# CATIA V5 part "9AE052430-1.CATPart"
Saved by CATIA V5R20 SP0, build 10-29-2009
Part number: 9AE052430-1
Revision: ANY
Definition: UNKNOWN
Nomenclature: 9AE052430-1
Source: Unknown
Bounding box of the stored display mesh (mm): x -8 to 8, y 0 to 76.999, z -8 to 8
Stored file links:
  C:\Users\Utente\Desktop\IO LAVORO\3D X SITO CF\CUMSA\3D files AE\AE 052430\9AE052430-1.CATPart
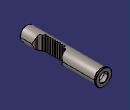
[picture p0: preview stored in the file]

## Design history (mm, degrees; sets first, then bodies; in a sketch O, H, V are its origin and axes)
Body1 "Chaflán2" (main body)
  Solid1: solid without history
